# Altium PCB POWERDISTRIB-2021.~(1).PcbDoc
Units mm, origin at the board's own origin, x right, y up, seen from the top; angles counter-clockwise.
Board outline 157.48 x 106.68 mm, 2 copper layers (Top Layer, Bottom Layer); 59 components, 25 nets, 145 pads, 64 vias.
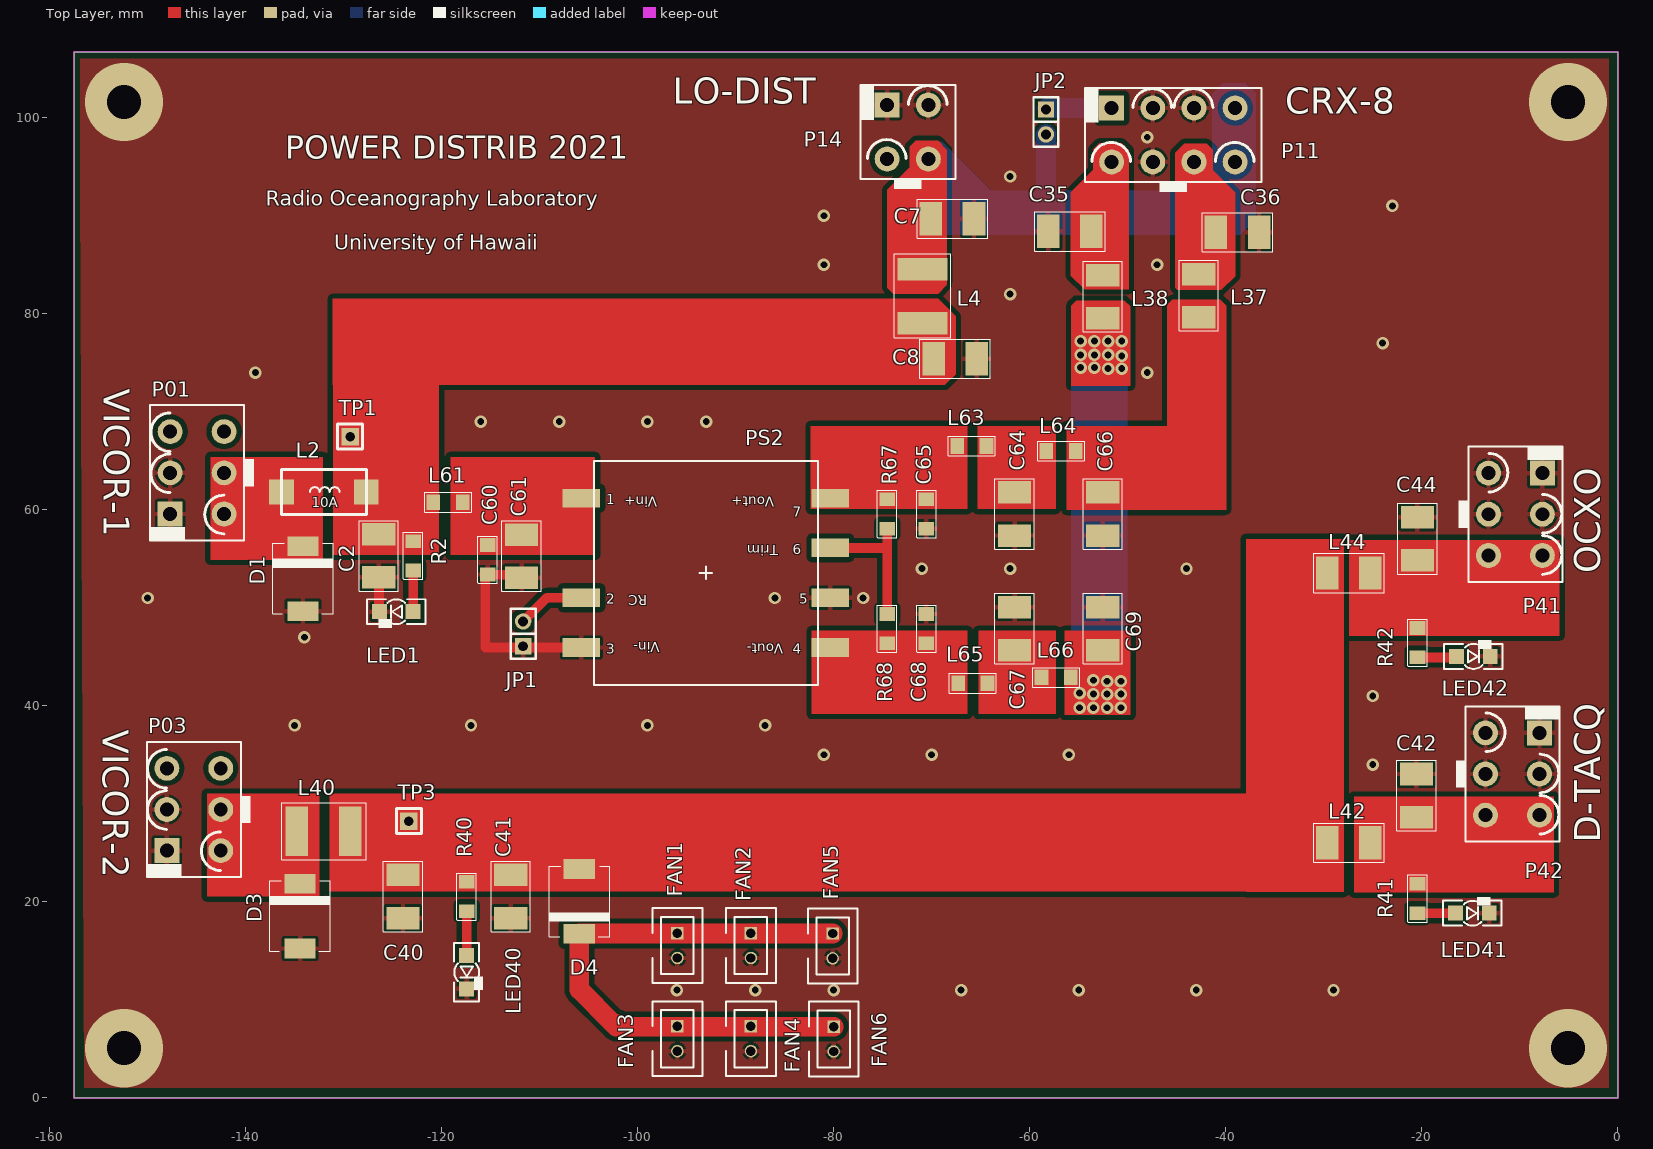
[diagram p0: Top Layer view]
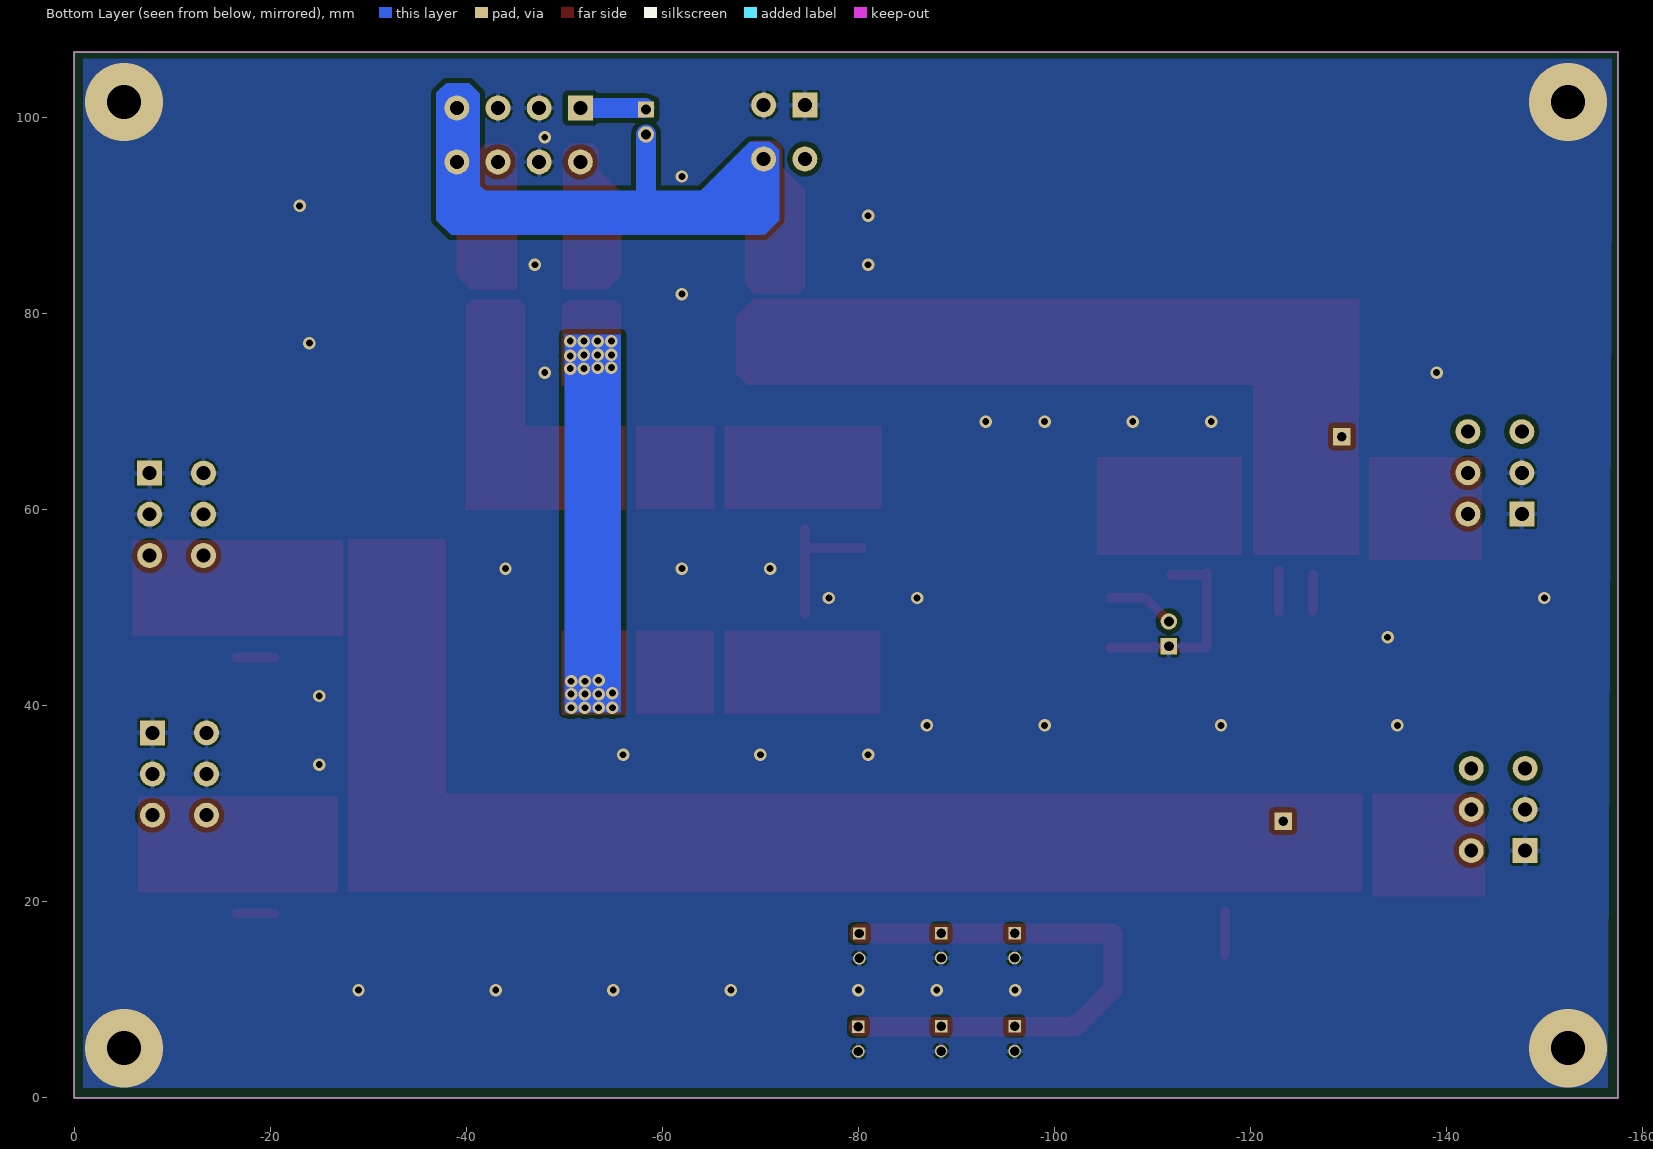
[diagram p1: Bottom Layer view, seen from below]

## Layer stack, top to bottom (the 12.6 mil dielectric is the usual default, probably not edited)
Top Solder: solder mask 0.0102, Solder Resist, Dk 3.5
Top Layer: signal copper 0.0356
Dielectric 1: dielectric 0.32, FR-4, Dk 4.8
Bottom Layer: signal copper 0.0356
Bottom Solder: solder mask 0.0102, Solder Resist, Dk 3.5

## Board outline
-157.48,0 -157.48,106.68 0,106.68 0,0

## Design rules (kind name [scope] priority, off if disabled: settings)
Clearance Clearance_1 [InPolygon] p1: gap=0.5 ignorepadtopadclearanceinfootprint=FALSE except(0: Arc-Hole Track-Hole SMDPad-Hole THPad-Hole Via-Hole Fill-Hole Poly-Hole Region-Hole Text-Hole)
Clearance [All] p2: gap=0.254 ignorepadtopadclearanceinfootprint=FALSE except(0: Arc-Hole Track-Hole SMDPad-Hole THPad-Hole Via-Hole Fill-Hole Poly-Hole Region-Hole Text-Hole)
ComponentClearance [All] p1 off: gap=0.254 collisioncheckmode=3 verticalgap=0.254 showdistances=FALSE
Height [All] p1 off: minheight=0 maxheight=25.4 prefheight=12.7
HoleSize [All] p1: absolutevalues=TRUE maxlimit=10 minlimit=0.025 maxpercent=80.000 minpercent=20.000
MinimumSolderMaskSliver [All] p1 off: minsoldermaskwidth=0.254
PolygonConnect [All] p1: thpad.connectstyle=Relief thpad.reliefconductorwidth=0.5 thpad.reliefentries=4 thpad.polygonreliefangle="90 Angle" thpad.airgapwidth=0.254 smdpad.connectstyle=Relief smdpad.reliefconductorwidth=0.5 smdpad.reliefentries=4 smdpad.polygonreliefangle="90 Angle" smdpad.airgapwidth=0.254 via.connectstyle=Direct via.reliefconductorwidth=0.5 via.reliefentries=4 via.polygonreliefangle="90 Angle" via.airgapwidth=0.254
RoomDefinition 2 [InComponentClass('2')] p1 off: confinementstyle=ConfineIn formatcopy=TRUE lockcomponents=FALSE outline -459.74,-302.56 -408.94,-302.56 -408.94,-277.16 -459.74,-277.16
RoomDefinition 1 [InComponentClass('1')] p2 off: confinementstyle=ConfineIn formatcopy=TRUE lockcomponents=FALSE outline -459.74,-302.56 -408.94,-302.56 -408.94,-277.16 -459.74,-277.16
RoutingVias [All] p1: holewidth=0.711 width=1.27 viastyle="Through Hole" minholewidth=0.711 minwidth=1.27 maxholewidth=3.5 maxwidth=8
SilkToSilkClearance [All] p1 off: silktosilkclearance=0.254
SilkToSolderMaskClearance [IsPad] p1 off: minsilkscreentomaskgap=0.254 clearancetoexposedcopper=TRUE
SolderMaskExpansion [All] p1: expansion=0.102
Width [All] p1: maxlimit=15 minlimit=0.254 preferedwidth=1 minimp=50.000000 maximp=50.000000 favimp=50.000000
24 further rules are at their usual default settings.

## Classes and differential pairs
component class 1: C60 C61 C64 C65 C66 C67 C68 C69 JP1 L61 L63 L64 L65 L66 PS2 R67 R68
component class 2: C2 C7 C8 C35 C36 C40 C41 C42 C44 D1 D3 D4 FAN1 FAN2 FAN3 FAN4 FAN5 FAN6 JP2 L2 L4 L37 L38 L40 L42 L44 LED1 LED40 LED41 LED42 MH1 MH4 MH7 MH8 MH9 P01 P03 P11 P14 P41 P42 R2 R40 R41 R42 TP1 TP3

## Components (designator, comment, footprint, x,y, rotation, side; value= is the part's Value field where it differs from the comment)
C2 "22uF 25V" 1812 -126.4,55.3 r270 top
C7 "22uF 25V" 1812 -67.88,89.7 r0 top
C8 "4.7uF" 1812 -67.6,75.4 r0 top
C35 "4.7uF" 1812 -55.9,88.4 r180 top
C36 "4.7uF" 1812 -38.8,88.3 r0 top
C40 "22uF 25V" 1812 -123.94,20.54 r270 top
C41 "4.7uF" 1812 -112.94,20.54 r270 top
C42 "22uF 25V" 1812 -20.54,30.84 r90 top
C44 "22uF 25V" 1812 -20.44,57.04 r90 top
C60 "100nF" 1206 -115.3,54.9 r270 top
C61 "22uF 25V" 1812 -111.84,55.27 r270 top
C64 "4.7uF" 1812 -61.54,59.57 r270 top
C65 "100nF" 1206 -70.54,59.57 r270 top
C66 "4.7uF" 1812 -52.54,59.57 r270 top
C67 "4.7uF" 1812 -61.54,47.87 r90 top
C68 "100nF" 1206 -70.54,47.87 r270 top
C69 "4.7uF" 1812 -52.54,47.87 r90 top
D1 "S5BC-13-F" SMC -134.14,52.97 r90 top
D3 "S5BC-13-F" SMC -134.44,18.54 r90 top
D4 "S5BC-13-F" SMC -105.94,20.04 r270 top
FAN1 "FAN1" SIP2-SHRD -95.94,15.54 r270 top
FAN2 "FAN2" SIP2-SHRD -88.44,15.54 r270 top
FAN3 "FAN3" SIP2-SHRD -95.94,6.04 r270 top
FAN4 "FAN4" SIP2-SHRD -88.44,6.04 r270 top
FAN5 "FAN1" SIP2-SHRD -80.1,15.5 r270 top
FAN6 "FAN2" SIP2-SHRD -80,6 r270 top
JP1 "" 2X2.54 -111.68,46.07 r180 top
JP2 "" 2X2.54 -58.34,100.84 r0 top
L2 "FER-10A" l3318 -132,61.8 r0 top
L4 "FER-8A" 2220 -70.94,81.84 r90 top
L37 "220uH" 1812 -42.74,81.84 r90 top
L38 "220uH" 1812 -52.54,81.74 r90 top
L40 "FER-8A" 2220 -132,27.2 r0 top
L42 "FER-3A" 1812 -27.44,26.04 r0 top
L44 "FER-3A" 1812 -27.44,53.54 r0 top
L61 "Ferrite" 1206 -119.34,60.77 r0 top
L63 "Ferrite" 1206 -65.9,66.5 r0 top
L64 "Ferrite" 1206 -56.8,66 r0 top
L65 "Ferrite" 1206 -65.8,42.3 r0 top
L66 "Ferrite" 1206 -57.3,42.9 r0 top
LED1 "12V BUS" LED1206 -122.9,49.6 r180 top
LED40 "+5V" LED1206 -117.44,14.54 r270 top
LED41 "D-tAcq" LED1206 -16.54,18.84 r0 top
LED42 "OSC" LED1206 -16.44,45.04 r0 top
P01 "12V" MFTJR2X3 -144.94,63.77 r90 top
P03 "13.5V" MFTJR2X3 -145.28,29.42 r90 top
P11 "RX POWER" MFTJR2X4 -45.34,98.24 r0 top
P14 "LO SPLIT" MFTJR2X2 -72.44,98.54 r0 top
P41 "D-tAcq" MFTJR2X3 -10.44,59.54 r270 top
P42 "OSCILLATOR" MFTJR2X3 -10.74,33.04 r270 top
PS2 "CC6-1212DR-E" DCDC-CC6/B -93.04,53.57 r0 top
R2 "4.99K" 1206 -122.9,55.3 r270 top
R40 "4.99K" 1206 -117.44,20.54 r270 top
R41 "4.99K" 1206 -20.44,20.34 r270 top
R42 "4.99K" 1206 -20.44,46.44 r270 top
R67 "Rdown" 1206 -74.54,59.57 r270 top
R68 "Rup" 1206 -74.54,47.87 r270 top
TP1 "+12V" TP -129.34,67.47 r0 top
TP3 "+13.5V" TP -123.34,28.24 r0 top

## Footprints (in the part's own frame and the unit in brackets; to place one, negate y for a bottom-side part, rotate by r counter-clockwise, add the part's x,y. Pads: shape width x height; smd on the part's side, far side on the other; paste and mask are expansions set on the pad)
2X2.54 [mm]
  rect 1.67x1.67 hole 1: 1(0,0)
  round 1.67 hole 1: 2(0,-2.54)
  silkscreen extent -1.27,-3.81 1.27,1.27, body extent -1.26,-3.8 1.28,1.28, height 9.54
1206 [mm]
  rect 1.4x1.6 smd mask+0.05: 1(-1.5,0) 2(1.5,0)
  silkscreen extent -2.4,-1 2.4,1, body extent -1.6,-0.8 1.6,0.8, height 1
1812 [mm]
  rect 2.3x3.4 smd: 1(-2.2,0) 2(2.2,0)
  silkscreen extent -3.6,-2 3.6,2, body extent -2.25,-1.6 2.25,1.6, height 1.6
2220 [mm]
  rect 2.3x5.1 smd: 1(-2.8,0) 2(2.7,0)
  silkscreen extent -4.3,-2.9 4.3,2.9, body extent -2.86,-2.53 2.84,2.47, height 2.3
DCDC-CC6/B [mm]
  rect 3.81x1.905 smd: 1(-12.7,7.62) 2(-12.7,-2.54) 3(-12.7,-7.62) 4(12.7,-7.62) 5(12.7,-2.54) 6(12.7,2.54) 7(12.7,7.62)
  silkscreen extent -11.43,-11.43 11.43,11.43, body extent -13.08,-10.55 13.08,10.55, height 8.8
l3318 [mil]
  rect 100x100 smd: 1(-170,0) 2(170,0)
  silkscreen extent -170,-90 170,90
LED1206 [mil]
  rect 60x60 smd: 1(0,0) 2(135,0)
  silkscreen extent -50,-50 185,65
MFTJR2X2 [mm]
  rect 2.54x2.54 hole 1.422: 1(-2.1,2.75)
  round 2.54 hole 1.422: 2(2.1,2.75) 3(-2.1,-2.75) 4(2.1,-2.75)
  silkscreen extent -4.85,-5.8 4.85,4.85, body extent -5.2,-6.07 5.2,4.93, height 12.8
MFTJR2X3 [mm]
  rect 2.54x2.54 hole 1.422: 1(-4.2,2.75)
  round 2.54 hole 1.422: 2(0,2.75) 3(4.2,2.75) 4(-4.2,-2.75) 5(0,-2.75) 6(4.2,-2.75)
  silkscreen extent -6.95,-5.79 6.9,4.85, body extent -7.3,-5.92 7.3,5.08, height 12.8
MFTJR2X4 [mm]
  rect 2.54x2.54 hole 1.422: 1(-6.3,2.75)
  round 2.54 hole 1.422: 2(-2.1,2.75) 3(2.1,2.75) 4(6.3,2.75) 5(-6.3,-2.75) 6(-2.1,-2.75) 7(2.1,-2.75) 8(6.3,-2.75)
  silkscreen extent -9.05,-5.8 9,4.85, body extent -9.4,-6.2 9.4,4.8, height 12.8
SIP2-SHRD [mil]
  rect 50x50 hole 38: 1(-50,0)
  round 50 hole 38: 2(50,0)
  silkscreen extent -150,-100 150,100
SMC [mm]
  rect 2x3.2 smd: A(-3.304,0) K(3.304,0)
  silkscreen extent -3.6,-3.1 3.6,3.1, body extent -4.05,-3.13 4.08,3.17, height 2.62
TP [mil]
  rect 70x70 hole 38: TP(0,0)
  silkscreen extent -50,-50 50,50

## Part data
C2 C7 C42 C44 C61 C64 C66 C67 C68 C69: library part C1206
C8 C35 C36 C41: library part CAP1206
C40: library part "CAPACITOR POL"
C60 C65: library part CAP_SHORT
D1 D3 D4: library part DIODE2
FAN1 FAN2 FAN3 FAN4 FAN5 FAN6: library part "HEADER 2_0"
JP1 JP2: library part STRAP
L2 L4 L40: library part FERRITE1812_0
L37 L38 L61 L63 L64 L65 L66: library part INDUCTOR
L42 L44: library part FERRITE_0
LED1: library part LED_1
LED40 LED41 LED42: library part LED_0
P01 P03 P41 P42: library part "HEADER 3X2_0"
P11: library part "HEADER 4X2_0"
P14: library part "HEADER 2X2_5"
PS2: library part "CONV +-15V_1"
R2 R40 R41 R42: library part RES1206
R67 R68: library part R1206
TP1 TP3: library part TP

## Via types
v1: diameter 1.27, hole 0.7, Top Layer to Bottom Layer, 60 vias
v2: diameter 8, hole 3.5, Top Layer to Bottom Layer, 4 vias

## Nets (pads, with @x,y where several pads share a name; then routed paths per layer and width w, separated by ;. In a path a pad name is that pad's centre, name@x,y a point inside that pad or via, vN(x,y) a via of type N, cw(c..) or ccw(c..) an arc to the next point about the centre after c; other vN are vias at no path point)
12VA1: C2.1 C8.1 L2.2 L4.1 L61.1 R2.1 TP1.TP | length 3.5
  Top Layer w1: -129.34,64.37 -129.04,64.07
  Top Layer w2: -129.34,64.37 TP1.TP
12VA2: C60.1 C61.1 L61.2 PS2.1
FANS: D4.K FAN1.1 FAN2.1 FAN3.1 FAN4.1 FAN5.1 FAN6.1 | length 67.2
  Top Layer w2: -102.17,7.27 FAN6.1 ; -102.17,7.54 -102.44,7.54 -105.94,11.04 D4.K -105.906,16.77 FAN5.1 ; FAN2.1 FAN5.1@-80.14,16.81
GND: C2.2 C7.2 C8.2 C35.2 C36.2 C40.2 C41.2 C42.2 C44.2 C60.2 C61.2 C64.2 C65.2 C66.2 C67.2 C68.1 C69.2 D1.A D3.A FAN1.2 FAN2.2 FAN3.2 FAN4.2 FAN5.2 FAN6.2 JP1.1 LED1.2 LED40.2 LED41.2 LED42.2 P01.1 P01.2 P03.1 P03.2 P11.2 P11.3 P11.6 P14.1 P14.2 P41.1 P41.2 P41.4 P41.5 P42.1 P42.2 P42.4 P42.5 PS2.3 PS2.5 | length 24.9
  Top Layer w1: LED1.2@-126.4,49.671 C2.2@-126.4,53.43 ; -115.54,45.97 -115.54,53.57 -115.44,53.37 C61.2@-111.94,53.37 ; -115.52,45.95 PS2.3
  other v1: -96,11 -88,11 -80,11 -67,11 -55,11 -43,11 -29,11 -25,34 -81,35 -70,35 -56,35 -135,38 -117,38 -99,38 -87,38 -25,41 -134,47 -150,51 -86,51 -77,51 -71,54 -62,54 -44,54 -116,69 -108,69 -99,69 -93,69 -139,74 -48,74 -24,77 -62,82 -81,85 -47,85 -81,90 -23,91 -62,94 -48,98
  other v2: -152.4,5.08 -5.08,5.08 -152.4,101.6 -5.08,101.6
NetC42_1: C42.1 L42.2 P42.3 P42.6 R41.1
NetD3_K: D3.K L40.1 P03.4 P03.5
NetJP1_2: JP1.2 PS2.2 | length 6.9
  Top Layer w1: JP1.2 -109.26,51.03 PS2.2
NetLED1_1: LED1.1 R2.2 | length 4.2
  Top Layer w1: LED1.1 R2.2
NetLED40_1: LED40.1 R40.2 | length 4.5
  Top Layer w1: LED40.1 R40.2
NetLED41_1: LED41.1 R41.2 | length 3.9
  Top Layer w1: R41.2 LED41.1
NetLED42_1: LED42.1 R42.2 | length 3.9
  Top Layer w1: R42.2 LED42.1@-16.54,44.94
NetPS2_6: PS2.6 R67.2 R68.1 | length 14.6
  Top Layer w1: PS2.6 -74.78,56.11 -74.54,55.87 ; R68.1 -74.54,55.87 ; R67.2 -74.54,55.87
PANT1: JP2.1 P11.1 | length 6.6
  Bottom Layer w2: JP2.1@-58.19,100.99 P11.1
V12IN1: D1.K L2.1 P01.4 P01.5
V12REC3: C7.1 JP2.2 L4.2 P11.4 P11.8 P14.4 | length 7.5
  Bottom Layer w2: -58.34,90.84 JP2.2
V13OUT4: C40.1 C41.1 D4.A L40.2 L42.1 L44.1 R40.1 TP3.TP
V13OUT9: C44.1 L44.2 P41.3 P41.6 R42.1
VCC1: C65.1 L63.1 PS2.7 R67.1
VCC2: C64.1 L63.2 L64.1
VCC3: C66.1 L37.1 L64.2
VCC5: C36.1 L37.2 P11.7
VEE1: C68.2 L65.1 PS2.4 R68.2
VEE2: C67.1 L65.2 L66.1
VEE3: C69.1 L38.1 L66.2
  other v1: -54.9,39.8 -53.5,39.8 -52.1,39.8 -50.7,39.8 -53.5,41.2 -52.1,41.2 -50.7,41.2 -54.9,41.3 -52.1,42.5 -50.7,42.5 -53.5,42.6 -52,74.4 -50.6,74.4 -54.8,74.5 -53.4,74.5 -50.6,75.7 -54.8,75.8 -53.4,75.8 -52,75.8 -54.8,77.2 -53.4,77.2 -52,77.2 -50.6,77.2
VEE5: C35.1 L38.2 P11.5
pads on no net: P01.3 P01.6 P03.3 P03.6 P14.3

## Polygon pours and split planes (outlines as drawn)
GND on Bottom Layer "Bottom Layer-No Net" (solid, remove dead copper, pour order 0): -156.44,1.04 -0.94,1.04 -0.94,106.04 -156.94,106.04
GND on Top Layer "Bottom Layer-No Net" (solid, remove dead copper, pour order 2): -156.44,1.04 -0.94,1.04 -0.94,106.04 -156.94,106.04

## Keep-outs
Keep-Out Layer:
  lines w0.2: -157.49,-0.01 -157.49,106.69 0.01,106.69 0.01,-0.01 -157.49,-0.01

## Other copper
Top Layer:
  region net VEE3: -49.7,47.67 -56.44,47.67 -56.44,39.07 -49.7,39.07
  region net VEE2: -57.34,47.67 -65.24,47.67 -65.24,39.17 -57.34,39.17
  region net VEE1: -66.34,47.67 -82.24,47.67 -82.24,39.17 -66.34,39.17
  region net VCC3: -40.1,68.57 -56.24,68.57 -56.24,59.97 -40.1,59.97
  region net VCC2: -57.34,68.57 -65.34,68.57 -65.34,60.07 -57.34,60.07
  region net VCC1: -66.34,68.57 -82.34,68.57 -82.34,60.07 -66.34,60.07
  region net 12VA2: -104.34,65.39 -119.1,65.39 -119.1,55.39 -104.34,55.39
  region net 12VA1: -120.24,74.5 -131.1,74.5 -131.1,55.39 -120.24,55.39
  region net V12IN1: -132.1,65.39 -143.6,65.39 -143.6,54.89 -132.1,54.89
  region net NetC42_1: -6.511,30.735 -26.911,30.735 -26.911,20.935 -6.511,20.935
  region net V13OUT9: -5.94,56.94 -27.44,56.94 -27.44,47.14 -5.94,47.14
  region net NetD3_K: -132.44,31.04 -143.94,31.04 -143.94,20.54 -132.44,20.54
  region net V13OUT4: -29.94,31.04 -131.44,31.04 -131.44,21.04 -29.94,21.04
  region net V13OUT4: -27.94,57.04 -37.94,57.04 -37.94,21 -27.94,21
  region net VCC3: -45.94,80.94 -45.44,81.44 -40.54,81.44 -39.94,80.84 -39.94,60 -45.94,60
  region net VEE3: -55.74,80.84 -55.24,81.34 -50.34,81.34 -49.74,80.74 -49.74,72.64 -55.74,72.64
  region net 12VA1: -69.34,81.54 -67.54,79.74 -67.54,73.84 -68.64,72.74 -131.1,72.74 -131.1,81.54
  region net V12REC3: -69.34,97.64 -68.44,96.74 -68.44,82.94 -69.34,82.04 -73.94,82.04 -74.54,82.64 -74.54,92.64 -74.04,93.14 -72.24,94.94 -72.24,97.04 -71.64,97.64
  region net VEE5: -50.6,97.4 -49.9,96.7 -49.9,82.5 -54.4,82.5 -55.8,83.9 -55.8,92.4 -55.3,92.9 -53.5,94.7 -53.5,96.8 -52.9,97.4
  region net VCC5: -44.24,97.34 -45.14,96.44 -45.14,82.64 -44.94,82.44 -40.44,82.44 -39.04,83.84 -39.04,92.34 -39.54,92.84 -41.34,94.64 -41.34,96.74 -41.94,97.34
Bottom Layer:
  region net VEE3: -50,77.9 -55.8,77.9 -55.8,39.3 -50,39.3
  region net V12REC3: -71.328,97.269 -71.94,96.657 -71.94,89.54 -70.44,88.04 -38.44,88.04 -36.94,89.54 -36.94,102.54 -37.94,103.54 -40.305,103.54 -41.398,102.448 -41.398,93.082 -41.94,92.54 -63.94,92.54 -68.94,97.54 -70.94,97.54

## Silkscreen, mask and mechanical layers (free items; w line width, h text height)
Top Overlay:
  text "LO-DIST" at -96.44,100.54 h4.5
  text "CRX-8" at -33.94,99.54 h4.5
  text "POWER DISTRIB 2021" at -135.94,95.04 h4
  text "Radio Oceanography Laboratory" at -137.94,91.04 h1.52
  text "University of Hawaii" at -130.94,86.54 h1.52
  text "VICOR-1" at -155.34,72.37 h4.5 r270
  text "OCXO" at -0.94,53.54 h4.5 r90
  text "VICOR-2" at -155.44,37.54 h4.5 r270
  text "D-TACQ" at -0.94,26.04 h4.5 r90
Mechanical 5:
  lines w0.127: -76.297,-89.05 -76.297,-80.369 ; -37.189,-73.544 80.114,-73.544 ; -37.189,-66.719 80.114,-66.719 ; -37.189,-55.629 80.114,-55.629 ; -37.189,-51.363 80.114,-51.363 ; -37.189,-47.097 80.114,-47.097 ; -37.189,-42.832 80.114,-42.832 ; -13.814,-59.894 -13.814,-38.566 ; 3.684,-80.369 3.684,-59.894 ; 43.882,-59.894 43.882,-38.566 ; 62.905,-59.894 62.905,-38.566 ; 80.114,-38.566 -76.297,-38.566 ; -76.297,-80.369 -76.297,-38.566 ; -76.297,-80.369 -37.189,-80.369 ; -76.297,-80.369 80.114,-80.369 ; -76.297,-38.566 -37.189,-38.566 ; -37.189,-80.369 -37.189,-59.894 ; -37.189,-80.369 80.114,-80.369 ; -37.189,-80.369 -37.189,-38.566 ; -37.189,-80.369 -37.189,-38.566 ; -37.189,-59.894 80.114,-59.894 ; -37.189,-59.894 80.114,-59.894 ; 62.046,-80.369 62.046,-66.719 ; 62.046,-80.369 80.114,-80.369 ; 62.046,-80.369 62.046,-66.719 ; 62.046,-73.544 62.046,-66.719 ; 62.046,-73.544 80.114,-73.544 ; 62.046,-73.544 62.046,-66.719 ; 62.046,-66.719 80.114,-66.719 ; 62.046,-66.719 80.114,-66.719 ; 80.114,-80.369 80.114,-59.894 ; 80.114,-80.369 80.114,-66.719 ; 80.114,-73.544 80.114,-66.719
  lines w0.5: -206.877,-89.038 -76.277,-89.038 80.123,-89.038 80.123,120.962 -206.877,120.962 ; -193.877,-84.038 -193.877,125.962
  text "Radio / Oceanography / Laboratory" at -70.35,-53.156 h4
  text "Indice" at -33.128,-58.485 h1.76
  text "Modification" at 5.841,-58.485 h1.76
  text "Date" at 49.515,-58.485 h1.76
  text "Dessine par" at 65.07,-58.567 h1.5
  text "Edition" at -36.218,-64.496 h1.76
  text ":" at -16.28,-64.496 h1.76
  text "CARTE POWER-DISTRIB-2021" at 7.523,-65.138 h1.8
  text "Dessinateur" at -36.218,-70.507 h1.76
  text "Folio" at 62.921,-70.507 h1.8
  text ":" at -16.28,-70.528 h1.76
  text ":" at 71.39,-70.528 h1.76
  text "1/1" at 73.767,-70.904 h1.76
  text "RONVEL" at -13.212,-71.019 h1.95
  text ":" at -16.28,-77.121 h1.76
  text "Date" at -36.218,-77.172 h1.76
  text "Ind" at 62.921,-77.172 h1.95
  text "22/07/21" at -14.327,-78.288 h1.8
Mechanical 7:
  text "PLAN DE CABLAGE" at 11.523,-71.638 h4
Mechanical 9:
  text "PLAN DE PERCAGE" at 17.123,-71.538 h4
Drill Drawing:
  circle w0.1: c-183.774,-29.009 r0.772
  lines w0.1: -185.89,-34.299 -86.363,-34.299 ; -185.89,-16.924 -86.363,-16.924 ; -173.55,-37.774 -173.55,-13.449 ; -160.38,-37.774 -160.38,-13.449 ; -133.547,-37.774 -133.547,-13.449 ; -122.249,-37.774 -122.249,-13.449 ; -105.67,-37.774 -105.67,-13.449 ; -185.89,-37.774 -86.363,-37.774 -86.363,-13.449 -185.89,-13.449 -185.89,-37.774 ; -184.546,-33.256 -183.002,-33.256 -183.002,-31.712 -184.546,-31.712 -184.546,-33.256 ; -184.546,-24.762 -183.002,-24.762 -183.774,-26.306 -184.546,-24.762 ; -184.546,-22.445 -184.16,-22.445 -184.16,-22.831 -183.388,-22.831 -183.388,-22.445 -183.002,-22.445 -183.002,-21.673 -183.388,-21.673 -183.388,-21.287 -184.16,-21.287 -184.16,-21.673 -184.546,-21.673 -184.546,-22.445 ; -184.546,-19.356 -183.774,-18.97 -183.002,-19.356 -183.388,-18.584 -183.002,-17.812 -183.774,-18.198 -184.546,-17.812 -184.16,-18.584 -184.546,-19.356
  text "Symbol" at -183.805,-15.881 h1.67
  text "Count" at -172.507,-15.881 h1.67
  text "Hole Size" at -159.337,-15.881 h1.67
  text "Plated" at -132.504,-15.881 h1.67
  text "Hole Type" at -121.206,-15.881 h1.67
  text "Technology" at -104.628,-15.881 h1.67
  text "4" at -172.507,-19.356 h1.39
  text "1,000mm (39,37mil)" at -159.337,-19.356 h1.39
  text "PTH" at -132.504,-19.356 h1.39
  text "Round" at -121.206,-19.356 h1.39
  text "(Mixed)" at -104.628,-19.356 h1.39
  text "4" at -172.507,-22.831 h1.39
  text "3,500mm (137,80mil)" at -159.337,-22.831 h1.39
  text "PTH" at -132.504,-22.831 h1.39
  text "Round" at -121.206,-22.831 h1.39
  text "v800h350m810" at -104.628,-22.831 h1.39
  text "14" at -172.507,-26.306 h1.39
  text "0,965mm (38,00mil)" at -159.337,-26.306 h1.39
  text "PTH" at -132.504,-26.306 h1.39
  text "Round" at -121.206,-26.306 h1.39
  text "(Mixed)" at -104.628,-26.306 h1.39
  text "36" at -172.507,-29.781 h1.39
  text "1,422mm (56,00mil)" at -159.337,-29.781 h1.39
  text "PTH" at -132.504,-29.781 h1.39
  text "Round" at -121.206,-29.781 h1.39
  text "(Mixed)" at -104.628,-29.781 h1.39
  text "60" at -172.507,-33.256 h1.39
  text "0,700mm (27,56mil)" at -159.337,-33.256 h1.39
  text "PTH" at -132.504,-33.256 h1.39
  text "Round" at -121.206,-33.256 h1.39
  text "v127h70m64" at -104.628,-33.256 h1.39
  text "118 Total" at -172.507,-36.731 h1.39
  text "Matiere FR4 16/10eme / TECHNO 2 COUCHES / Cuivre 35 microns 2 faces / Vernis selectif vert 2 faces / Serigraphie blanche 2 faces / Finition NiAu" at -186.94,-73.96 h3

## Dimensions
-157.49,-0.01 to -157.49,106.69 on Drill Drawing
-157.49,106.69 to 0.01,106.7 on Drill Drawing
